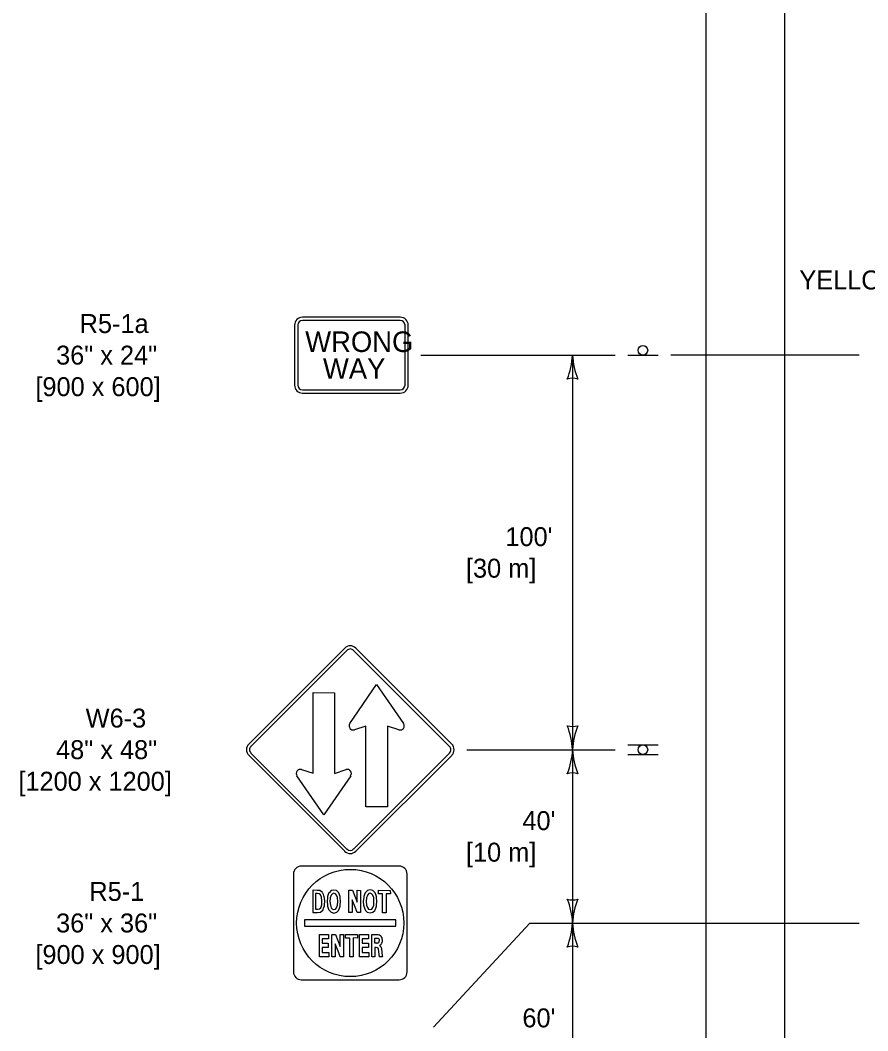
# Model space of a CAD drawing. Extents: x 49991.4 to 50021, y 49987.6 to 50011.4.
# Drawn here: x 50005.142 to 50007.828, y 49990.189 to 49993.39 of the extents above; entities that cross this region are included whole.
import ezdxf

# ---------------------------------------------------------------- set-up
doc = ezdxf.new("R2010")
doc.units = 0
for name, color, linetype in [('Level 1', 7, 'Continuous'), ('Level 2', 7, 'Continuous'), ('Level 3', 7, 'Continuous')]:
    doc.layers.add(name, color=color, linetype=linetype)

msp = doc.modelspace()

# ---------------------------------------------------------------- linework, layer by layer
at = {"layer": 'Level 1'}
for p, q in [((50007.315, 49988.2392), (50007.315, 49998.6725)), ((50007.565, 49988.2392), (50007.565, 49998.6725)), ((50006.3462, 49992.4493), (50006.0362, 49992.4493)), ((50006.3462, 49992.4393), (50006.0362, 49992.4393)), ((50006.0112, 49992.4243), (50006.0112, 49992.2343)), ((50006.0212, 49992.4243), (50006.0212, 49992.2343)), ((50006.3612, 49992.2343), (50006.3612, 49992.4243)), ((50006.3712, 49992.2343), (50006.3712, 49992.4243)), ((50007.0671, 49992.3293), (50007.1631, 49992.3293)), ((50006.0362, 49992.2193), (50006.3462, 49992.2193)), ((50006.0362, 49992.2093), (50006.3462, 49992.2093)), ((50005.866, 49991.0969), (50006.17, 49991.401)), ((50005.8729, 49991.0899), (50006.177, 49991.394)), ((50006.1983, 49991.3939), (50006.5022, 49991.0898)), ((50006.2055, 49991.4009), (50006.5094, 49991.0968)), ((50006.1864, 49991.1618), (50006.2712, 49991.2856)), ((50006.2712, 49991.2856), (50006.3564, 49991.162)), ((50006.0697, 49991.0045), (50006.0699, 49991.26)), ((50006.0699, 49991.26), (50006.1379, 49991.2599)), ((50006.1379, 49991.2599), (50006.1377, 49991.0044)), ((50006.2373, 49991.154), (50006.2009, 49991.1424)), ((50006.2373, 49990.8986), (50006.2373, 49991.154)), ((50006.3419, 49991.1423), (50006.3053, 49991.1539)), ((50006.3053, 49991.1539), (50006.3055, 49990.8985)), ((50007.0671, 49991.0945), (50007.1631, 49991.0945)), ((50006.17, 49990.7576), (50005.8659, 49991.0615)), ((50006.177, 49990.7645), (50005.8728, 49991.0686)), ((50006.5023, 49991.0687), (50006.1983, 49990.7646)), ((50006.5095, 49991.0614), (50006.2052, 49990.7576)), ((50007.0671, 49991.064), (50007.1631, 49991.064)), ((50006.1039, 49990.873), (50006.0187, 49990.9966)), ((50006.0334, 49991.0163), (50006.0697, 49991.0045)), ((50006.1889, 49990.9966), (50006.1039, 49990.873)), ((50006.1377, 49991.0044), (50006.1743, 49991.0163)), ((50006.3055, 49990.8985), (50006.2375, 49990.8986)), ((50006.3426, 49990.7103), (50006.0324, 49990.7103)), ((50006.0074, 49990.6855), (50006.0072, 49990.3753)), ((50006.3674, 49990.3751), (50006.3676, 49990.6853)), ((50006.069, 49990.6329), (50006.0688, 49990.6277)), ((50006.0688, 49990.6277), (50006.0688, 49990.6261)), ((50006.0688, 49990.6261), (50006.069, 49990.6249)), ((50006.069, 49990.6209), (50006.0688, 49990.6167)), ((50006.0688, 49990.6167), (50006.0688, 49990.6127)), ((50006.0688, 49990.6127), (50006.0688, 49990.6017)), ((50006.069, 49990.6339), (50006.069, 49990.6329)), ((50006.0822, 49990.6337), (50006.069, 49990.6339)), ((50006.069, 49990.6249), (50006.069, 49990.6209)), ((50006.0778, 49990.6207), (50006.0776, 49990.6167)), ((50006.0776, 49990.6167), (50006.0776, 49990.6129)), ((50006.0776, 49990.6129), (50006.0778, 49990.6017)), ((50006.0778, 49990.6235), (50006.0778, 49990.6209)), ((50006.0842, 49990.6235), (50006.0778, 49990.6235)), ((50006.0914, 49990.6329), (50006.0822, 49990.6337)), ((50006.0888, 49990.6227), (50006.0842, 49990.6235)), ((50006.0928, 49990.6191), (50006.0888, 49990.6227)), ((50006.0988, 49990.6275), (50006.0914, 49990.6329)), ((50006.096, 49990.6119), (50006.0928, 49990.6191)), ((50006.0978, 49990.6005), (50006.096, 49990.6119)), ((50006.0996, 49990.6261), (50006.0988, 49990.6275)), ((50006.1004, 49990.6249), (50006.0996, 49990.6261)), ((50006.1024, 49990.6207), (50006.1004, 49990.6249)), ((50006.1042, 49990.6167), (50006.1024, 49990.6207)), ((50006.105, 49990.6127), (50006.1042, 49990.6167)), ((50006.1068, 49990.6017), (50006.105, 49990.6127)), ((50006.1154, 49990.6113), (50006.114, 49990.5987)), ((50006.1156, 49990.6131), (50006.1154, 49990.6113)), ((50006.1178, 49990.6201), (50006.1156, 49990.6141)), ((50006.1156, 49990.6141), (50006.1156, 49990.6131)), ((50006.1198, 49990.6255), (50006.1178, 49990.6201)), ((50006.1214, 49990.6271), (50006.1198, 49990.6255)), ((50006.127, 49990.6327), (50006.1214, 49990.6271)), ((50006.1244, 49990.6101), (50006.1232, 49990.5983)), ((50006.1268, 49990.6185), (50006.1244, 49990.6101)), ((50006.131, 49990.6231), (50006.1268, 49990.6185)), ((50006.1358, 49990.6347), (50006.127, 49990.6327)), ((50006.1358, 49990.6245), (50006.131, 49990.6231)), ((50006.1444, 49990.6329), (50006.1358, 49990.6347)), ((50006.1404, 49990.6229), (50006.1358, 49990.6245)), ((50006.1442, 49990.6187), (50006.1404, 49990.6229)), ((50006.147, 49990.6107), (50006.1442, 49990.6187)), ((50006.15, 49990.6271), (50006.1444, 49990.6329)), ((50006.1478, 49990.5985), (50006.147, 49990.6107)), ((50006.1514, 49990.6255), (50006.15, 49990.6271)), ((50006.1514, 49990.6253), (50006.1514, 49990.6255)), ((50006.1518, 49990.6253), (50006.1514, 49990.6253)), ((50006.1536, 49990.6199), (50006.1518, 49990.6253)), ((50006.1554, 49990.6145), (50006.1536, 49990.6199)), ((50006.1558, 49990.6133), (50006.1554, 49990.6145)), ((50006.156, 49990.6111), (50006.1558, 49990.6133)), ((50006.157, 49990.5979), (50006.156, 49990.6111)), ((50006.156, 49990.6111), (50006.156, 49990.6111)), ((50006.183, 49990.6231), (50006.183, 49990.6339)), ((50006.183, 49990.6339), (50006.1944, 49990.6339)), ((50006.183, 49990.5761), (50006.183, 49990.6231)), ((50006.1944, 49990.6339), (50006.2092, 49990.5959)), ((50006.2092, 49990.5959), (50006.2094, 49990.6341)), ((50006.2094, 49990.6341), (50006.22, 49990.6337)), ((50006.22, 49990.6337), (50006.2198, 49990.5763)), ((50006.2304, 49990.6115), (50006.229, 49990.5989)), ((50006.2306, 49990.6135), (50006.2304, 49990.6115)), ((50006.2326, 49990.6203), (50006.2306, 49990.6145)), ((50006.2306, 49990.6145), (50006.2306, 49990.6135)), ((50006.2346, 49990.6257), (50006.2326, 49990.6203)), ((50006.2364, 49990.6273), (50006.2346, 49990.6257)), ((50006.2418, 49990.6331), (50006.2364, 49990.6273)), ((50006.2392, 49990.6103), (50006.2382, 49990.5985)), ((50006.2418, 49990.6187), (50006.2392, 49990.6103)), ((50006.2506, 49990.6351), (50006.2418, 49990.6331)), ((50006.246, 49990.6233), (50006.2418, 49990.6187)), ((50006.2506, 49990.6247), (50006.246, 49990.6233)), ((50006.2594, 49990.6331), (50006.2506, 49990.6351)), ((50006.2554, 49990.6231), (50006.2506, 49990.6247)), ((50006.2592, 49990.6189), (50006.2554, 49990.6231)), ((50006.2618, 49990.6109), (50006.2592, 49990.6189)), ((50006.265, 49990.6273), (50006.2594, 49990.6331)), ((50006.2628, 49990.5987), (50006.2618, 49990.6109)), ((50006.2664, 49990.6259), (50006.265, 49990.6273)), ((50006.2664, 49990.6257), (50006.2664, 49990.6259)), ((50006.2666, 49990.6255), (50006.2664, 49990.6257)), ((50006.2684, 49990.6201), (50006.2666, 49990.6255)), ((50006.2704, 49990.6147), (50006.2684, 49990.6201)), ((50006.2708, 49990.6137), (50006.2704, 49990.6147)), ((50006.271, 49990.6113), (50006.2708, 49990.6137)), ((50006.272, 49990.5981), (50006.271, 49990.6113)), ((50006.271, 49990.6113), (50006.271, 49990.6113)), ((50006.2768, 49990.6339), (50006.3144, 49990.6337)), ((50006.277, 49990.6229), (50006.2768, 49990.6339)), ((50006.29, 49990.6229), (50006.277, 49990.6229)), ((50006.2898, 49990.5629), (50006.29, 49990.6229)), ((50006.3146, 49990.6229), (50006.3012, 49990.6229)), ((50006.3012, 49990.6229), (50006.3012, 49990.5629)), ((50006.3144, 49990.6337), (50006.3146, 49990.6229)), ((50006.0688, 49990.6017), (50006.0688, 49990.6001)), ((50006.0688, 49990.6001), (50006.069, 49990.5867)), ((50006.069, 49990.5867), (50006.0688, 49990.5841)), ((50006.0688, 49990.5841), (50006.069, 49990.5773)), ((50006.069, 49990.5773), (50006.0688, 49990.5727)), ((50006.0778, 49990.6015), (50006.0776, 49990.5999)), ((50006.0776, 49990.6001), (50006.0776, 49990.5867)), ((50006.0776, 49990.5867), (50006.0776, 49990.5843)), ((50006.0776, 49990.5841), (50006.0776, 49990.5775)), ((50006.0776, 49990.5775), (50006.0778, 49990.5741)), ((50006.0778, 49990.5741), (50006.0846, 49990.5739)), ((50006.0846, 49990.5739), (50006.09, 49990.5751)), ((50006.09, 49990.5751), (50006.094, 49990.5787)), ((50006.094, 49990.5787), (50006.0972, 49990.5877)), ((50006.0972, 49990.5877), (50006.0978, 49990.6005)), ((50006.0978, 49990.5999), (50006.0974, 49990.6015)), ((50006.1014, 49990.5727), (50006.1032, 49990.5773)), ((50006.1032, 49990.5773), (50006.1056, 49990.5841)), ((50006.1056, 49990.5841), (50006.1058, 49990.5867)), ((50006.1058, 49990.5867), (50006.1066, 49990.6001)), ((50006.1066, 49990.6001), (50006.1068, 49990.6017)), ((50006.114, 49990.5987), (50006.114, 49990.5983)), ((50006.114, 49990.5983), (50006.115, 49990.5865)), ((50006.115, 49990.5865), (50006.1152, 49990.5863)), ((50006.1152, 49990.5863), (50006.1154, 49990.5831)), ((50006.1154, 49990.5831), (50006.1156, 49990.5831)), ((50006.1156, 49990.5831), (50006.1176, 49990.5775)), ((50006.1176, 49990.5773), (50006.1194, 49990.5717)), ((50006.1232, 49990.5983), (50006.1246, 49990.5867)), ((50006.1246, 49990.5867), (50006.127, 49990.5787)), ((50006.127, 49990.5787), (50006.1308, 49990.5739)), ((50006.1308, 49990.5739), (50006.1356, 49990.5725)), ((50006.1356, 49990.5725), (50006.1406, 49990.5741)), ((50006.1406, 49990.5741), (50006.1442, 49990.5785)), ((50006.1442, 49990.5785), (50006.147, 49990.5867)), ((50006.147, 49990.5867), (50006.1478, 49990.5983)), ((50006.1516, 49990.5719), (50006.1538, 49990.5771)), ((50006.1538, 49990.5771), (50006.1558, 49990.5831)), ((50006.1538, 49990.5771), (50006.1538, 49990.5771)), ((50006.1558, 49990.5865), (50006.157, 49990.5979)), ((50006.1558, 49990.5831), (50006.1558, 49990.5865)), ((50006.1558, 49990.5831), (50006.1558, 49990.5831)), ((50006.1828, 49990.5633), (50006.183, 49990.5761)), ((50006.2048, 49990.5753), (50006.1938, 49990.6039)), ((50006.1938, 49990.6039), (50006.1938, 49990.5763)), ((50006.1938, 49990.5763), (50006.1938, 49990.5633)), ((50006.2094, 49990.5631), (50006.2048, 49990.5753)), ((50006.2198, 49990.5763), (50006.2198, 49990.5631)), ((50006.229, 49990.5989), (50006.229, 49990.5985)), ((50006.229, 49990.5985), (50006.23, 49990.5867)), ((50006.23, 49990.5867), (50006.23, 49990.5867)), ((50006.23, 49990.5867), (50006.2302, 49990.5833)), ((50006.2302, 49990.5833), (50006.2302, 49990.5833)), ((50006.2302, 49990.5833), (50006.2326, 49990.5777)), ((50006.2326, 49990.5777), (50006.2344, 49990.5721)), ((50006.2382, 49990.5985), (50006.2392, 49990.5871)), ((50006.2392, 49990.5871), (50006.2418, 49990.5789)), ((50006.2418, 49990.5789), (50006.2458, 49990.5741)), ((50006.2458, 49990.5741), (50006.2506, 49990.5727)), ((50006.2506, 49990.5727), (50006.2556, 49990.5743)), ((50006.2556, 49990.5743), (50006.2592, 49990.5789)), ((50006.2592, 49990.5789), (50006.2618, 49990.5869)), ((50006.2618, 49990.5869), (50006.2628, 49990.5987)), ((50006.2666, 49990.5721), (50006.2686, 49990.5775)), ((50006.2686, 49990.5775), (50006.2688, 49990.5777)), ((50006.2688, 49990.5777), (50006.2706, 49990.5833)), ((50006.2706, 49990.5833), (50006.2708, 49990.5867)), ((50006.2706, 49990.5833), (50006.2706, 49990.5833)), ((50006.2708, 49990.5867), (50006.272, 49990.5981)), ((50006.069, 49990.5647), (50006.0686, 49990.5631)), ((50006.0686, 49990.5631), (50006.0836, 49990.5633)), ((50006.0688, 49990.5727), (50006.069, 49990.5715)), ((50006.069, 49990.5715), (50006.069, 49990.5647)), ((50006.0836, 49990.5633), (50006.0936, 49990.5647)), ((50006.0936, 49990.5647), (50006.1012, 49990.5715)), ((50006.1012, 49990.5715), (50006.1014, 49990.5727)), ((50006.1194, 49990.5717), (50006.1198, 49990.5717)), ((50006.1198, 49990.5717), (50006.1198, 49990.5715)), ((50006.1198, 49990.5715), (50006.1214, 49990.5701)), ((50006.1214, 49990.5701), (50006.1266, 49990.5643)), ((50006.1266, 49990.5643), (50006.1356, 49990.5619)), ((50006.1356, 49990.5619), (50006.1448, 49990.5643)), ((50006.1448, 49990.5643), (50006.1502, 49990.5701)), ((50006.1502, 49990.5701), (50006.1516, 49990.5715)), ((50006.1516, 49990.5715), (50006.1516, 49990.5719)), ((50006.1516, 49990.5719), (50006.1516, 49990.5719)), ((50006.1938, 49990.5633), (50006.1828, 49990.5633)), ((50006.2198, 49990.5631), (50006.2094, 49990.5631)), ((50006.2344, 49990.5721), (50006.2346, 49990.5721)), ((50006.2346, 49990.5721), (50006.2348, 49990.5717)), ((50006.2348, 49990.5717), (50006.236, 49990.5703)), ((50006.236, 49990.5703), (50006.2416, 49990.5645)), ((50006.2416, 49990.5645), (50006.2506, 49990.5623)), ((50006.2506, 49990.5623), (50006.2596, 49990.5645)), ((50006.2596, 49990.5645), (50006.2652, 49990.5703)), ((50006.2652, 49990.5703), (50006.2666, 49990.5717)), ((50006.2666, 49990.5717), (50006.2666, 49990.5721)), ((50006.2666, 49990.5721), (50006.2666, 49990.5721)), ((50006.3012, 49990.5629), (50006.2898, 49990.5629)), ((50006.3324, 49990.5403), (50006.0424, 49990.5405)), ((50006.0424, 49990.5405), (50006.0426, 49990.5203)), ((50006.0426, 49990.5203), (50006.3324, 49990.5201)), ((50006.3324, 49990.5201), (50006.3324, 49990.5403)), ((50006.0896, 49990.4855), (50006.0896, 49990.4937)), ((50006.0896, 49990.4937), (50006.1188, 49990.4935)), ((50006.0898, 49990.4637), (50006.0896, 49990.4855)), ((50006.1188, 49990.4801), (50006.0984, 49990.4805)), ((50006.0984, 49990.4805), (50006.0984, 49990.4661)), ((50006.1188, 49990.4935), (50006.1188, 49990.4801)), ((50006.129, 49990.4831), (50006.1292, 49990.4939)), ((50006.1292, 49990.4361), (50006.129, 49990.4831)), ((50006.1292, 49990.4939), (50006.1406, 49990.4937)), ((50006.1406, 49990.4937), (50006.1556, 49990.4557)), ((50006.1556, 49990.4557), (50006.1554, 49990.4939)), ((50006.1554, 49990.4939), (50006.1662, 49990.4939)), ((50006.1662, 49990.4939), (50006.1662, 49990.4361)), ((50006.1728, 49990.4937), (50006.2104, 49990.4937)), ((50006.1728, 49990.4827), (50006.1728, 49990.4937)), ((50006.186, 49990.4827), (50006.1728, 49990.4827)), ((50006.1858, 49990.4231), (50006.186, 49990.4827)), ((50006.1972, 49990.4829), (50006.197, 49990.4231)), ((50006.2106, 49990.4827), (50006.1972, 49990.4829)), ((50006.2104, 49990.4937), (50006.2106, 49990.4827)), ((50006.2166, 49990.4853), (50006.2166, 49990.4937)), ((50006.2166, 49990.4937), (50006.2458, 49990.4937)), ((50006.2168, 49990.4637), (50006.2166, 49990.4853)), ((50006.2458, 49990.4805), (50006.2254, 49990.4805)), ((50006.2254, 49990.4805), (50006.2254, 49990.4661)), ((50006.2458, 49990.4937), (50006.2458, 49990.4805)), ((50006.2562, 49990.4937), (50006.2728, 49990.4939)), ((50006.2564, 49990.4379), (50006.2562, 49990.4937)), ((50006.265, 49990.4663), (50006.2652, 49990.4823)), ((50006.2652, 49990.4823), (50006.2676, 49990.4823)), ((50006.2676, 49990.4823), (50006.2732, 49990.4823)), ((50006.2728, 49990.4939), (50006.2764, 49990.4935)), ((50006.2728, 49990.4823), (50006.2756, 49990.4821)), ((50006.2756, 49990.4821), (50006.2772, 49990.4811)), ((50006.2764, 49990.4935), (50006.2804, 49990.4923)), ((50006.2772, 49990.4811), (50006.2788, 49990.4787)), ((50006.2788, 49990.4787), (50006.2788, 49990.4775)), ((50006.2788, 49990.4775), (50006.2794, 49990.4747)), ((50006.2804, 49990.4923), (50006.2842, 49990.4895)), ((50006.2842, 49990.4895), (50006.2868, 49990.4847)), ((50006.2872, 49990.4845), (50006.2874, 49990.4831)), ((50006.2874, 49990.4831), (50006.288, 49990.4795)), ((50006.288, 49990.4795), (50006.2886, 49990.4775)), ((50006.2886, 49990.4775), (50006.2884, 49990.4747)), ((50006.0896, 49990.4315), (50006.0898, 49990.4555)), ((50006.0898, 49990.4555), (50006.0898, 49990.4637)), ((50006.0984, 49990.4661), (50006.118, 49990.4661)), ((50006.118, 49990.4529), (50006.0984, 49990.4529)), ((50006.0984, 49990.4529), (50006.0984, 49990.4363)), ((50006.118, 49990.4661), (50006.118, 49990.4529)), ((50006.151, 49990.4353), (50006.14, 49990.4637)), ((50006.14, 49990.4637), (50006.14, 49990.4361)), ((50006.2168, 49990.4555), (50006.2168, 49990.4637)), ((50006.2168, 49990.4315), (50006.2168, 49990.4555)), ((50006.2254, 49990.4661), (50006.245, 49990.4659)), ((50006.245, 49990.4529), (50006.2254, 49990.4531)), ((50006.2254, 49990.4531), (50006.2254, 49990.4365)), ((50006.245, 49990.4659), (50006.245, 49990.4529)), ((50006.272, 49990.4661), (50006.265, 49990.4663)), ((50006.2652, 49990.4523), (50006.265, 49990.4229)), ((50006.2702, 49990.4523), (50006.2652, 49990.4523)), ((50006.2742, 49990.4519), (50006.2698, 49990.4523)), ((50006.272, 49990.4661), (50006.2728, 49990.4661)), ((50006.2752, 49990.4665), (50006.2728, 49990.4661)), ((50006.2762, 49990.4505), (50006.2742, 49990.4519)), ((50006.277, 49990.4673), (50006.2752, 49990.4665)), ((50006.2774, 49990.4471), (50006.2762, 49990.4505)), ((50006.2784, 49990.4695), (50006.277, 49990.4673)), ((50006.2802, 49990.4227), (50006.2774, 49990.4471)), ((50006.2786, 49990.4711), (50006.2784, 49990.4695)), ((50006.2794, 49990.4747), (50006.2786, 49990.4711)), ((50006.2818, 49990.4593), (50006.28, 49990.4587)), ((50006.28, 49990.4587), (50006.2828, 49990.4569)), ((50006.2842, 49990.4615), (50006.2818, 49990.4593)), ((50006.2828, 49990.4569), (50006.2852, 49990.4535)), ((50006.286, 49990.4641), (50006.2842, 49990.4615)), ((50006.2852, 49990.4535), (50006.2856, 49990.4523)), ((50006.2856, 49990.4523), (50006.2868, 49990.4479)), ((50006.2864, 49990.4649), (50006.286, 49990.4641)), ((50006.2876, 49990.4687), (50006.2864, 49990.4651)), ((50006.2864, 49990.4649), (50006.2864, 49990.4651)), ((50006.2868, 49990.4477), (50006.2868, 49990.4479)), ((50006.2868, 49990.4477), (50006.2874, 49990.4377)), ((50006.2882, 49990.4703), (50006.2876, 49990.4687)), ((50006.2884, 49990.4747), (50006.2882, 49990.4703)), ((50006.0896, 49990.4229), (50006.0896, 49990.4315)), ((50006.1194, 49990.4231), (50006.0896, 49990.4229)), ((50006.0984, 49990.4363), (50006.1192, 49990.4363)), ((50006.1192, 49990.4363), (50006.1194, 49990.4231)), ((50006.129, 49990.4231), (50006.1292, 49990.4361)), ((50006.1398, 49990.4231), (50006.129, 49990.4231)), ((50006.14, 49990.4361), (50006.1398, 49990.4231)), ((50006.1556, 49990.4231), (50006.151, 49990.4353)), ((50006.166, 49990.4231), (50006.1556, 49990.4231)), ((50006.1662, 49990.4361), (50006.166, 49990.4231)), ((50006.197, 49990.4231), (50006.1858, 49990.4231)), ((50006.2164, 49990.4229), (50006.2168, 49990.4315)), ((50006.2464, 49990.4231), (50006.2164, 49990.4229)), ((50006.2254, 49990.4365), (50006.2462, 49990.4363)), ((50006.2462, 49990.4363), (50006.2464, 49990.4231)), ((50006.256, 49990.4231), (50006.2562, 49990.4277)), ((50006.265, 49990.4229), (50006.256, 49990.4231)), ((50006.2562, 49990.4369), (50006.2564, 49990.4379)), ((50006.2562, 49990.4277), (50006.2562, 49990.4369)), ((50006.2894, 49990.4231), (50006.2802, 49990.4227)), ((50006.2874, 49990.4377), (50006.2876, 49990.4369)), ((50006.2876, 49990.4369), (50006.2888, 49990.4275)), ((50006.2888, 49990.4275), (50006.2888, 49990.4275)), ((50006.2888, 49990.4275), (50006.2888, 49990.4275)), ((50006.2888, 49990.4275), (50006.2894, 49990.4231)), ((50006.0326, 49990.3503), (50006.3424, 49990.3501))]:
    msp.add_line(p, q, dxfattribs=at)
for centre, radius in [((50007.115, 49992.3446), 0.0152), ((50007.115, 49991.0793), 0.0152), ((50006.1875, 49990.5302), 0.1699)]:
    msp.add_circle(centre, radius, dxfattribs=at)
for centre, radius, start, end in [((50006.0361, 49992.4243), 0.025, 90, 180), ((50006.0361, 49992.4243), 0.015, 90, 180), ((50006.3461, 49992.4243), 0.025, 0, 90), ((50006.3461, 49992.4243), 0.015, 0, 90), ((50006.0361, 49992.2343), 0.025, 180, 270), ((50006.0361, 49992.2343), 0.015, 180, 270), ((50006.3461, 49992.2343), 0.025, 270, 0), ((50006.3461, 49992.2343), 0.015, 270, 0), ((50006.1876, 49991.3834), 0.025, 44.9951, 134.9951), ((50006.1876, 49991.3834), 0.015, 44.9951, 134.9951), ((50006.1969, 49991.1546), 0.0129, 145.58, 216.7114), ((50006.3458, 49991.1546), 0.0129, 323.2757, 34.5145), ((50006.1969, 49991.1546), 0.0129, 216.7145, 287.9533), ((50006.3458, 49991.1546), 0.0129, 252.0369, 323.2727), ((50005.8835, 49991.0794), 0.025, 134.9949, 224.9951), ((50005.8835, 49991.0794), 0.015, 134.9949, 224.9951), ((50006.4916, 49991.0793), 0.015, 314.9951, 44.9951), ((50006.4916, 49991.0793), 0.025, 314.9951, 44.9951), ((50006.0294, 49991.0041), 0.0129, 143.2757, 214.5145), ((50006.0294, 49991.0041), 0.0129, 72.0369, 143.2727), ((50006.1782, 49991.004), 0.0129, 36.7145, 107.9533), ((50006.1782, 49991.004), 0.0129, 325.5801, 36.7114), ((50006.1875, 49990.7753), 0.025, 224.9955, 314.9951), ((50006.1875, 49990.7753), 0.015, 224.9955, 314.9951), ((50006.0325, 49990.6853), 0.025, 89.9905, 179.9905), ((50006.3426, 49990.6853), 0.025, 359.9905, 89.9905), ((50006.0325, 49990.3753), 0.025, 179.9905, 269.9905), ((50006.3425, 49990.3752), 0.025, 269.9905, 359.9905)]:
    msp.add_arc(centre, radius, start, end, dxfattribs=at)
at = {"layer": 'Level 3'}
for p, q in [((50006.4112, 49992.3293), (50007.0271, 49992.3293)), ((50006.892, 49992.3293), (50006.892, 49991.0793)), ((50007.8, 49992.3293), (50007.2031, 49992.3293)), ((50006.5566, 49991.0793), (50007.027, 49991.0793)), ((50006.892, 49991.0793), (50006.892, 49990.5299)), ((50006.757, 49990.5299), (50006.4516, 49990.2006)), ((50006.757, 49990.5299), (50007.8, 49990.5299)), ((50006.892, 49990.5299), (50006.892, 49989.8293))]:
    msp.add_line(p, q, dxfattribs=at)
for centre, radius, start, end in [((50006.6593, 49992.3408), 0.233, 337.9228, 357.1727), ((50007.1141, 49992.3385), 0.2223, 182.3605, 202.544), ((50006.892, 49992.2011), 0.0548, 72.1388, 107.8612), ((50006.892, 49991.2075), 0.0548, 252.1388, 287.8612), ((50006.6593, 49991.0678), 0.233, 2.8273, 22.0772), ((50007.1141, 49991.0701), 0.2223, 157.456, 177.6395), ((50006.6699, 49991.0885), 0.2223, 337.456, 357.6395), ((50007.1247, 49991.0908), 0.233, 182.8273, 202.0772), ((50006.892, 49990.9511), 0.0548, 72.1388, 107.8612), ((50006.6699, 49990.5208), 0.2223, 2.3605, 22.544), ((50006.892, 49990.6581), 0.0548, 252.1388, 287.8612), ((50007.1247, 49990.5184), 0.233, 157.9228, 177.1727), ((50006.6593, 49990.5414), 0.233, 337.9228, 357.1727), ((50007.1141, 49990.5391), 0.2223, 182.3605, 202.544), ((50006.892, 49990.4017), 0.0548, 72.1388, 107.8612)]:
    msp.add_arc(centre, radius, start, end, dxfattribs=at)

# ---------------------------------------------------------------- texts
at = {"layer": 'Level 1'}
for s, p in [('WRONG', (50006.0448, 49992.3394)), ('WAY', (50006.101, 49992.2544))]:
    msp.add_text(s, height=0.065, dxfattribs=at).set_placement(p)
at = {"layer": 'Level 2'}
for s, p in [('YELLOW', (50007.6109, 49992.5375)), ('R5-1a', (50005.3301, 49992.3994)), ('36" x 24"', (50005.2554, 49992.2994)), ('[900 x 600]', (50005.1898, 49992.1994)), ("100'", (50006.6792, 49991.7243)), ('[30 m]', (50006.5543, 49991.6243)), ('W6-3', (50005.3491, 49991.1494)), ('48" x 48"', (50005.2554, 49991.0494)), ('[1200 x 1200]', (50005.1359, 49990.9494)), ("40'", (50006.7331, 49990.8246)), ('[10 m]', (50006.5543, 49990.7246)), ("60'", (50006.7331, 49990.1996))]:
    msp.add_text(s, height=0.06, dxfattribs=at).set_placement(p)
for s, p in [('R5-1', (50005.3609, 49990.6003)), ('36" x 36"', (50005.2554, 49990.5003)), ('[900 x 900]', (50005.1898, 49990.4003))]:
    msp.add_text(s, height=0.06, rotation=0.0174, dxfattribs=at).set_placement(p)

doc.saveas('drawing.dxf')
